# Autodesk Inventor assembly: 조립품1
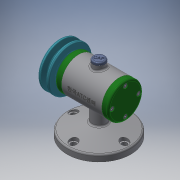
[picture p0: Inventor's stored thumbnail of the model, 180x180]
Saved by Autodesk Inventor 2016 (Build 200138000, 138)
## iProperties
Created: 2018-12
Part Number: 조립품1
Document SubType Name: Assembly
Designer: Administrator
Author: Administrator
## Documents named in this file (15)
- C:\Users\Administrator\Desktop\주재현\481208V1018\답안조립품.iam
- C:\Users\Administrator\Desktop\주재현\481208V1018\부품1.ipt
- C:\Users\Administrator\Desktop\주재현\481208V1018\V벨트풀리.ipt
- C:\Users\Administrator\Desktop\주재현\481208V1018\축.ipt
- C:\Users\Administrator\Desktop\주재현\481208V1018\키 3 x 3 x 12.ipt
- C:\Users\Administrator\Desktop\주재현\481208V1018\너트 M8.ipt
- 너트 M8.ipt
- C:\Users\Administrator\Desktop\주재현\481208V1018\와셔 8x17.ipt
- C:\Users\Administrator\Desktop\주재현\481208V1018\스프링와셔 8.ipt
- C:\Users\Administrator\Desktop\주재현\481208V1018\베어링 15 x 32 x 9.ipt
- C:\Users\Administrator\Desktop\주재현\481208V1018\앞커버.ipt
- C:\Users\Administrator\Desktop\주재현\481208V1018\오일 실 15 25 7.ipt
- C:\Users\Administrator\Desktop\주재현\481208V1018\뒤커버.ipt
- C:\Users\Administrator\Desktop\주재현\481208V1018\볼트 M4 x 12.ipt
- C:\Users\Administrator\Desktop\주재현\481208V1018\고무캡.ipt
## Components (2 placed, 2 different names)
1. V벨트풀리:1
2. 고무캡:1
